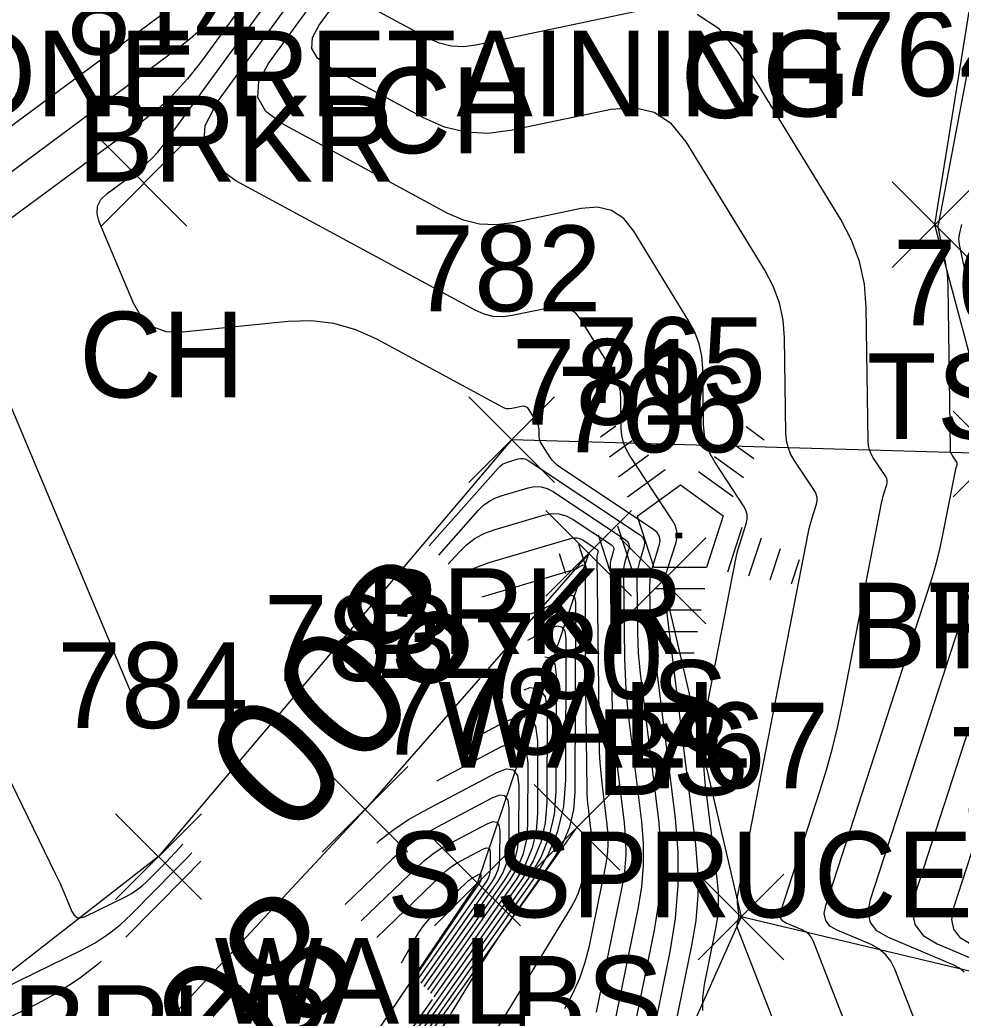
# Model space of a CAD drawing. Extents: x 1650836 to 1652450, y 332578 to 333908.
# Drawn here: x 1652049.38 to 1652071.34, y 332707.88 to 332730.94 of the extents above; entities that cross this region are included whole.
import ezdxf

# ---------------------------------------------------------------- set-up
doc = ezdxf.new("R2010")
doc.units = 0
for name, color, linetype in [('L_A', 7, 'Continuous'), ('L_C', 7, 'Continuous'), ('L_I', 7, 'Continuous'), ('L_TIC', 7, 'Continuous'), ('LAWE', 7, 'Continuous'), ('LELB', 7, 'Continuous'), ('LSOGCMA', 7, 'Continuous'), ('LSOGCMA_T', 7, 'Continuous'), ('LSOGCMI', 7, 'Continuous'), ('LTC', 7, 'Continuous'), ('LW', 7, 'Continuous')]:
    doc.layers.add(name, color=color, linetype=linetype)

msp = doc.modelspace()

# ---------------------------------------------------------------- linework, layer by layer
at = {"layer": 'L_TIC'}
for points in [[(1652051.274, 332726.131), (1652053.274, 332728.131)], [(1652053.274, 332726.131), (1652051.274, 332728.131)], [(1652069.729, 332725.162), (1652071.729, 332727.162)], [(1652071.729, 332725.162), (1652069.729, 332727.162)], [(1652059.852, 332720.144), (1652061.852, 332722.144)], [(1652061.852, 332720.144), (1652059.852, 332722.144)], [(1652071.158, 332719.813), (1652073.158, 332721.813)], [(1652073.158, 332719.813), (1652071.158, 332721.813)], [(1652071.158, 332719.813), (1652073.158, 332721.813)], [(1652073.158, 332719.813), (1652071.158, 332721.813)], [(1652061.652, 332717.494), (1652063.652, 332719.494)], [(1652063.652, 332717.494), (1652061.652, 332719.494)], [(1652063.381, 332716.853), (1652065.381, 332718.853)], [(1652065.381, 332716.853), (1652063.381, 332718.853)], [(1652056.435, 332711.519), (1652058.435, 332713.519)], [(1652058.435, 332711.519), (1652056.435, 332713.519)], [(1652061.38, 332711.103), (1652063.38, 332713.103)], [(1652063.38, 332711.103), (1652061.38, 332713.103)], [(1652051.615, 332710.419), (1652053.615, 332712.419)], [(1652053.615, 332710.419), (1652051.615, 332712.419)], [(1652059.057, 332709.801), (1652061.057, 332711.801)], [(1652061.057, 332709.801), (1652059.057, 332711.801)], [(1652065.208, 332709.013), (1652067.208, 332711.013)], [(1652067.208, 332709.013), (1652065.208, 332711.013)], [(1652065.208, 332709.013), (1652067.208, 332711.013)], [(1652067.208, 332709.013), (1652065.208, 332711.013)]]:
    msp.add_lwpolyline(points, dxfattribs=at)
at = {"layer": 'LAWE'}
msp.add_lwpolyline([(1652113.729, 332729.971), (1652105.001, 332721.607), (1652097.708, 332720.127), (1652089.433, 332715.148), (1652085.656, 332707.437), (1652080.101, 332708.542), (1652073.451, 332709.446), (1652072.158, 332720.813), (1652060.852, 332721.144), (1652052.615, 332711.419), (1652043.802, 332704.554), (1652032.724, 332702.068), (1652025.188, 332702.458), (1652014.024, 332714.079), (1651995.915, 332712.612)], dxfattribs=at)
at = {"layer": 'LELB'}
for points in [[(1652072.158, 332720.813), (1652070.729, 332726.162), (1652073.187, 332741.436)], [(1652064.381, 332717.853), (1652066.208, 332710.013), (1652062.736, 332702.235), (1652040.399, 332672.943)], [(1652040.117, 332681.915), (1652050.149, 332694.94), (1652062.38, 332712.103)]]:
    msp.add_lwpolyline(points, dxfattribs=at)
at = {"layer": 'LSOGCMA'}
for points in [[(1652054.097, 332732.112), (1652041.239, 332722.59)], [(1652059.376, 332718.24), (1652059.619, 332718.515), (1652059.802, 332718.695), (1652060.004, 332718.845), (1652060.226, 332718.965), (1652060.467, 332719.054), (1652061.599, 332719.389), (1652061.781, 332719.424), (1652061.958, 332719.418), (1652062.128, 332719.371), (1652062.292, 332719.284), (1652063.184, 332718.69), (1652063.214, 332718.664), (1652063.232, 332718.633), (1652063.238, 332718.598), (1652063.231, 332718.558), (1652063.18, 332718.391), (1652063.168, 332718.35), (1652063.161, 332718.307), (1652063.156, 332718.264), (1652063.155, 332718.221), (1652063.193, 332715.225), (1652063.203, 332714.846), (1652063.223, 332714.467), (1652063.254, 332714.089), (1652063.296, 332713.712), (1652063.483, 332712.204), (1652063.514, 332711.828), (1652063.515, 332711.453), (1652063.485, 332711.079), (1652063.424, 332710.706), (1652062.829, 332707.787)], [(1652072.286, 332716.76), (1652070.262, 332710.53), (1652070.196, 332710.153), (1652070.261, 332709.836), (1652070.457, 332709.58), (1652070.785, 332709.383), (1652073.122, 332708.394)], [(1652058.811, 332708.39), (1652060.536, 332710.848), (1652060.649, 332711.036), (1652060.729, 332711.233), (1652060.777, 332711.441), (1652060.794, 332711.659), (1652060.797, 332712.551), (1652060.773, 332712.734), (1652060.699, 332712.834), (1652060.576, 332712.853), (1652060.404, 332712.789), (1652059.097, 332712.1), (1652058.82, 332711.942), (1652058.556, 332711.765), (1652058.306, 332711.57), (1652058.068, 332711.357), (1652056.971, 332710.3)], [(1652048.634, 332708.171), (1652050.822, 332709.238), (1652051.14, 332709.41), (1652051.439, 332709.607), (1652051.721, 332709.828), (1652051.986, 332710.074), (1652053.007, 332711.108), (1652053.26, 332711.368), (1652053.392, 332711.508)]]:
    msp.add_lwpolyline(points, dxfattribs=at)
at = {"layer": 'LSOGCMI'}
for points in [[(1652070.398, 332707.235), (1652069.793, 332708.795), (1652069.7, 332708.981), (1652069.577, 332709.138), (1652069.424, 332709.266), (1652069.24, 332709.365), (1652068.446, 332709.701), (1652068.281, 332709.8), (1652068.181, 332709.93), (1652068.149, 332710.089), (1652068.182, 332710.279), (1652070.643, 332717.856), (1652070.721, 332718.11), (1652070.792, 332718.366), (1652070.854, 332718.625), (1652070.909, 332718.885), (1652071.207, 332720.418), (1652071.211, 332720.436), (1652071.215, 332720.454), (1652071.22, 332720.471), (1652071.225, 332720.489), (1652071.248, 332720.559), (1652071.251, 332720.576), (1652071.251, 332720.593), (1652071.247, 332720.609), (1652071.239, 332720.625), (1652071.135, 332720.782), (1652071.117, 332720.814), (1652071.104, 332720.847), (1652071.096, 332720.882), (1652071.093, 332720.919), (1652071.04, 332724.732), (1652071.034, 332724.872), (1652071.022, 332725.012), (1652071.003, 332725.151), (1652070.977, 332725.29), (1652070.804, 332726.102), (1652070.803, 332726.109), (1652070.803, 332726.117), (1652070.803, 332726.125), (1652070.805, 332726.132), (1652070.813, 332726.171), (1652070.816, 332726.186), (1652070.818, 332726.194), (1652073.605, 332740.882)], [(1652067.555, 332706.068), (1652066.133, 332709.735), (1652066.123, 332709.765), (1652066.119, 332709.795), (1652066.118, 332709.825), (1652066.122, 332709.855), (1652066.148, 332709.978), (1652066.153, 332710.009), (1652066.155, 332710.04), (1652066.155, 332710.071), (1652066.152, 332710.102), (1652066.124, 332710.327), (1652066.12, 332710.375), (1652066.12, 332710.423), (1652066.124, 332710.47), (1652066.131, 332710.518), (1652067.78, 332718.993), (1652067.797, 332719.076), (1652067.817, 332719.158), (1652067.839, 332719.239), (1652067.863, 332719.32), (1652067.966, 332719.642), (1652067.982, 332719.722), (1652067.981, 332719.798), (1652067.961, 332719.873), (1652067.924, 332719.944), (1652067.446, 332720.668), (1652067.362, 332720.816), (1652067.302, 332720.971), (1652067.265, 332721.133), (1652067.251, 332721.302), (1652067.22, 332723.519), (1652067.187, 332723.938), (1652067.1, 332724.342), (1652066.958, 332724.729), (1652066.762, 332725.101), (1652064.925, 332728.094), (1652064.587, 332728.513), (1652064.183, 332728.779), (1652063.713, 332728.89), (1652063.176, 332728.848), (1652060.826, 332728.357), (1652060.299, 332728.291), (1652059.785, 332728.319), (1652059.285, 332728.439), (1652058.799, 332728.652), (1652056.583, 332729.85), (1652056.321, 332730.046), (1652056.196, 332730.272), (1652056.211, 332730.53), (1652056.364, 332730.82), (1652057.317, 332732.13)], [(1652054.969, 332731.837), (1652053.596, 332729.95), (1652053.294, 332729.566), (1652052.966, 332729.209), (1652052.611, 332728.877), (1652052.23, 332728.572), (1652049.075, 332726.235), (1652048.539, 332725.715), (1652048.247, 332725.128), (1652048.199, 332724.474), (1652048.394, 332723.754), (1652052.211, 332714.673)], [(1652063.518, 332704.125), (1652064.552, 332709.197), (1652064.678, 332709.972), (1652064.741, 332710.75), (1652064.739, 332711.53), (1652064.674, 332712.313), (1652064.12, 332716.782), (1652064.107, 332716.899), (1652064.097, 332717.017), (1652064.091, 332717.136), (1652064.087, 332717.254), (1652064.081, 332717.728), (1652064.084, 332717.846), (1652064.097, 332717.963), (1652064.118, 332718.078), (1652064.148, 332718.192), (1652064.298, 332718.677), (1652064.317, 332718.789), (1652064.301, 332718.889), (1652064.25, 332718.977), (1652064.164, 332719.052), (1652061.982, 332720.505), (1652061.919, 332720.552), (1652061.861, 332720.604), (1652061.809, 332720.662), (1652061.762, 332720.726), (1652061.547, 332721.053), (1652061.526, 332721.09), (1652061.511, 332721.128), (1652061.501, 332721.169), (1652061.498, 332721.211), (1652061.495, 332721.384), (1652061.492, 332721.426), (1652061.483, 332721.467), (1652061.469, 332721.506), (1652061.449, 332721.543), (1652061.264, 332721.846), (1652061.229, 332721.888), (1652061.189, 332721.915), (1652061.141, 332721.926), (1652061.087, 332721.922), (1652060.857, 332721.874), (1652060.8, 332721.867), (1652060.745, 332721.87), (1652060.691, 332721.883), (1652060.638, 332721.906), (1652057.709, 332723.49), (1652057.216, 332723.713), (1652056.707, 332723.856), (1652056.182, 332723.919), (1652055.642, 332723.903), (1652053.177, 332723.653), (1652052.795, 332723.665), (1652052.477, 332723.782), (1652052.222, 332724.005), (1652052.029, 332724.335), (1652051.234, 332726.226), (1652051.182, 332726.419), (1652051.195, 332726.594), (1652051.273, 332726.752), (1652051.417, 332726.891), (1652052.121, 332727.413), (1652052.291, 332727.549), (1652052.45, 332727.697), (1652052.596, 332727.857), (1652052.731, 332728.028), (1652055.384, 332731.674)], [(1652065.316, 332707.826), (1652065.313, 332708.127), (1652065.354, 332708.433), (1652065.604, 332709.661), (1652065.654, 332709.968), (1652065.679, 332710.277), (1652065.678, 332710.586), (1652065.652, 332710.897), (1652065.373, 332713.149), (1652065.333, 332713.627), (1652065.33, 332714.104), (1652065.365, 332714.58), (1652065.439, 332715.054), (1652066.066, 332718.281), (1652066.09, 332718.396), (1652066.118, 332718.51), (1652066.148, 332718.623), (1652066.182, 332718.736), (1652066.325, 332719.184), (1652066.348, 332719.294), (1652066.346, 332719.401), (1652066.318, 332719.504), (1652066.266, 332719.604), (1652065.602, 332720.611), (1652065.485, 332720.817), (1652065.401, 332721.032), (1652065.35, 332721.258), (1652065.33, 332721.493), (1652065.312, 332722.807), (1652065.289, 332723.101), (1652065.228, 332723.383), (1652065.128, 332723.655), (1652064.991, 332723.915), (1652063.704, 332726.011), (1652063.468, 332726.305), (1652063.185, 332726.491), (1652062.856, 332726.569), (1652062.48, 332726.539), (1652060.884, 332726.206), (1652060.49, 332726.157), (1652060.106, 332726.177), (1652059.733, 332726.267), (1652059.369, 332726.427), (1652055.495, 332728.522), (1652055.116, 332728.804), (1652054.936, 332729.132), (1652054.957, 332729.505), (1652055.178, 332729.923), (1652056.556, 332731.817)], [(1652064.463, 332706.412), (1652065.061, 332709.343), (1652065.156, 332709.927), (1652065.203, 332710.514), (1652065.202, 332711.102), (1652065.152, 332711.691), (1652064.398, 332717.772), (1652064.397, 332717.781), (1652064.397, 332717.79), (1652064.398, 332717.8), (1652064.4, 332717.809), (1652064.407, 332717.846), (1652064.409, 332717.855), (1652064.411, 332717.864), (1652064.413, 332717.873), (1652064.416, 332717.882), (1652064.684, 332718.726), (1652064.713, 332718.867), (1652064.71, 332719.004), (1652064.676, 332719.136), (1652064.609, 332719.264), (1652063.607, 332720.783), (1652063.524, 332720.929), (1652063.464, 332721.083), (1652063.427, 332721.243), (1652063.413, 332721.411), (1652063.404, 332722.095), (1652063.39, 332722.263), (1652063.355, 332722.425), (1652063.299, 332722.58), (1652063.22, 332722.729), (1652062.484, 332723.929), (1652062.349, 332724.096), (1652062.187, 332724.203), (1652061.998, 332724.248), (1652061.783, 332724.231), (1652060.87, 332724.04), (1652060.645, 332724.012), (1652060.425, 332724.024), (1652060.212, 332724.075), (1652060.004, 332724.166), (1652054.407, 332727.193), (1652053.91, 332727.562), (1652053.675, 332727.991), (1652053.702, 332728.479), (1652053.992, 332729.027), (1652055.799, 332731.511)], [(1652063.873, 332731.157), (1652060.022, 332730.351), (1652059.73, 332730.315), (1652059.445, 332730.331), (1652059.168, 332730.397), (1652058.899, 332730.515), (1652057.671, 332731.179)], [(1652053.857, 332731.042), (1652053.704, 332730.847), (1652053.537, 332730.665), (1652053.357, 332730.497), (1652053.163, 332730.342), (1652046.173, 332725.165)], [(1652068.977, 332706.652), (1652067.895, 332709.44), (1652067.851, 332709.528), (1652067.793, 332709.602), (1652067.721, 332709.662), (1652067.635, 332709.708), (1652067.261, 332709.866), (1652067.183, 332709.913), (1652067.137, 332709.974), (1652067.121, 332710.049), (1652067.137, 332710.139), (1652068.048, 332712.943), (1652068.202, 332713.444), (1652068.341, 332713.95), (1652068.465, 332714.46), (1652068.573, 332714.973), (1652069.494, 332719.706), (1652069.504, 332719.756), (1652069.516, 332719.806), (1652069.53, 332719.855), (1652069.544, 332719.905), (1652069.607, 332720.101), (1652069.617, 332720.149), (1652069.616, 332720.196), (1652069.604, 332720.241), (1652069.581, 332720.284), (1652069.29, 332720.725), (1652069.24, 332720.815), (1652069.203, 332720.909), (1652069.18, 332721.008), (1652069.172, 332721.11), (1652069.129, 332724.231), (1652069.086, 332724.776), (1652068.972, 332725.3), (1652068.787, 332725.804), (1652068.532, 332726.287), (1652066.145, 332730.177), (1652065.706, 332730.722), (1652065.181, 332731.066)], [(1652072.297, 332721.02), (1652071.301, 332725.701), (1652071.292, 332725.76), (1652071.289, 332725.818), (1652071.292, 332725.877), (1652071.302, 332725.935), (1652071.354, 332726.168)], [(1652058.932, 332718.667), (1652060.545, 332720.489), (1652060.591, 332720.534), (1652060.641, 332720.572), (1652060.696, 332720.601), (1652060.756, 332720.624), (1652061.006, 332720.697), (1652061.067, 332720.709), (1652061.126, 332720.707), (1652061.184, 332720.691), (1652061.239, 332720.662), (1652063.838, 332718.931), (1652063.905, 332718.872), (1652063.945, 332718.804), (1652063.957, 332718.725), (1652063.942, 332718.637), (1652063.828, 332718.265), (1652063.803, 332718.172), (1652063.785, 332718.077), (1652063.775, 332717.982), (1652063.773, 332717.885), (1652063.788, 332716.645), (1652063.795, 332716.406), (1652063.808, 332716.167), (1652063.827, 332715.929), (1652063.853, 332715.692), (1652064.277, 332712.277), (1652064.331, 332711.629), (1652064.332, 332710.984), (1652064.281, 332710.341), (1652064.176, 332709.7), (1652062.756, 332702.736)], [(1652059.154, 332718.454), (1652060.082, 332719.502), (1652060.197, 332719.615), (1652060.323, 332719.708), (1652060.461, 332719.783), (1652060.612, 332719.839), (1652061.237, 332720.024), (1652061.391, 332720.053), (1652061.54, 332720.048), (1652061.683, 332720.009), (1652061.822, 332719.936), (1652063.511, 332718.811), (1652063.559, 332718.768), (1652063.588, 332718.718), (1652063.597, 332718.662), (1652063.587, 332718.598), (1652063.504, 332718.328), (1652063.485, 332718.261), (1652063.473, 332718.192), (1652063.466, 332718.123), (1652063.464, 332718.053), (1652063.489, 332716.036), (1652063.499, 332715.676), (1652063.518, 332715.317), (1652063.548, 332714.959), (1652063.587, 332714.602), (1652063.88, 332712.24), (1652063.923, 332711.729), (1652063.924, 332711.218), (1652063.883, 332710.71), (1652063.8, 332710.203), (1652062.868, 332705.633)], [(1652071.41, 332708.723), (1652071.302, 332708.813), (1652071.172, 332708.883), (1652069.631, 332709.536), (1652069.378, 332709.687), (1652069.226, 332709.885), (1652069.176, 332710.13), (1652069.227, 332710.42), (1652072.197, 332719.564)], [(1652062.093, 332707.879), (1652062.284, 332708.226), (1652062.444, 332708.585), (1652062.572, 332708.957), (1652062.667, 332709.341), (1652063.049, 332711.209), (1652063.087, 332711.448), (1652063.106, 332711.687), (1652063.106, 332711.927), (1652063.086, 332712.168), (1652062.966, 332713.133), (1652062.94, 332713.374), (1652062.92, 332713.616), (1652062.907, 332713.859), (1652062.9, 332714.101), (1652062.846, 332718.389), (1652062.846, 332718.405), (1652062.848, 332718.422), (1652062.851, 332718.438), (1652062.856, 332718.455), (1652062.875, 332718.519), (1652062.878, 332718.534), (1652062.876, 332718.548), (1652062.869, 332718.559), (1652062.857, 332718.57), (1652062.513, 332718.799), (1652062.45, 332718.832), (1652062.385, 332718.85), (1652062.317, 332718.852), (1652062.247, 332718.839), (1652060.322, 332718.27), (1652059.991, 332718.147), (1652059.686, 332717.982), (1652059.662, 332717.965)], [(1652060.165, 332717.481), (1652062.261, 332718.101), (1652062.293, 332718.112), (1652062.325, 332718.124), (1652062.357, 332718.137), (1652062.387, 332718.153), (1652062.509, 332718.217), (1652062.536, 332718.227), (1652062.555, 332718.224), (1652062.566, 332718.208), (1652062.57, 332718.18), (1652062.566, 332716.878), (1652062.565, 332716.65), (1652062.566, 332716.421), (1652062.567, 332716.193), (1652062.57, 332715.964), (1652062.608, 332712.978), (1652062.61, 332712.871), (1652062.616, 332712.765), (1652062.625, 332712.659), (1652062.637, 332712.554), (1652062.689, 332712.132), (1652062.698, 332712.026), (1652062.698, 332711.921), (1652062.69, 332711.816), (1652062.673, 332711.712), (1652062.506, 332710.895), (1652062.464, 332710.727), (1652062.408, 332710.564), (1652062.338, 332710.407), (1652062.254, 332710.255), (1652055.206, 332698.71)], [(1652053.402, 332697.865), (1652059.941, 332708.577), (1652060.165, 332708.937), (1652060.394, 332709.293), (1652060.629, 332709.646), (1652060.87, 332709.994), (1652061.844, 332711.382), (1652062.057, 332711.739), (1652062.21, 332712.114), (1652062.302, 332712.51), (1652062.334, 332712.924), (1652062.348, 332717.34), (1652062.334, 332717.443), (1652062.292, 332717.5), (1652062.222, 332717.51), (1652062.125, 332717.474), (1652061.677, 332717.239), (1652061.564, 332717.182), (1652061.449, 332717.132), (1652061.331, 332717.088), (1652061.211, 332717.049), (1652060.755, 332716.914)], [(1652050.432, 332686.428), (1652050.426, 332694.636), (1652050.441, 332694.864), (1652050.486, 332695.083), (1652050.561, 332695.294), (1652050.667, 332695.497), (1652051.151, 332696.289), (1652051.274, 332696.486), (1652051.399, 332696.681), (1652051.528, 332696.875), (1652051.66, 332697.066), (1652061.396, 332710.933), (1652061.709, 332711.457), (1652061.933, 332712.009), (1652062.069, 332712.59), (1652062.115, 332713.199), (1652062.126, 332716.499), (1652062.102, 332716.677), (1652062.03, 332716.776), (1652061.909, 332716.794), (1652061.74, 332716.732), (1652061.226, 332716.461)], [(1652051.332, 332696.788), (1652061.252, 332710.919), (1652061.532, 332711.387), (1652061.733, 332711.88), (1652061.854, 332712.398), (1652061.895, 332712.942), (1652061.904, 332715.658), (1652061.87, 332715.912), (1652061.768, 332716.052), (1652061.629, 332716.073)], [(1652061.15, 332715.313), (1652061.283, 332715.362), (1652061.505, 332715.328), (1652061.638, 332715.147), (1652061.682, 332714.818), (1652061.675, 332712.685), (1652061.638, 332712.207), (1652061.532, 332711.751), (1652061.356, 332711.317), (1652061.109, 332710.905), (1652052.704, 332698.932)], [(1652048.404, 332714.711), (1652050.206, 332711.026), (1652050.258, 332710.917), (1652050.309, 332710.808), (1652050.358, 332710.698), (1652050.406, 332710.587), (1652050.595, 332710.142), (1652050.65, 332710.051), (1652050.72, 332710.001), (1652050.806, 332709.993), (1652050.907, 332710.025), (1652051.845, 332710.483), (1652051.982, 332710.557), (1652052.11, 332710.641), (1652052.231, 332710.736), (1652052.345, 332710.842), (1652052.783, 332711.285), (1652052.892, 332711.397), (1652052.999, 332711.51), (1652053.105, 332711.625), (1652053.181, 332711.71)], [(1652060.154, 332714.277), (1652060.714, 332714.572), (1652061.041, 332714.692), (1652061.275, 332714.657), (1652061.414, 332714.466), (1652061.46, 332714.121), (1652061.455, 332712.429), (1652061.423, 332712.016), (1652061.331, 332711.621), (1652061.179, 332711.246), (1652060.966, 332710.891), (1652059.042, 332708.15)], [(1652058.965, 332708.23), (1652060.823, 332710.876), (1652061.002, 332711.176), (1652061.13, 332711.492), (1652061.208, 332711.824), (1652061.234, 332712.172), (1652061.239, 332713.598), (1652061.2, 332713.889), (1652061.083, 332714.049), (1652060.886, 332714.079), (1652060.611, 332713.978), (1652059.101, 332713.182)], [(1652072.374, 332713.955), (1652071.162, 332710.224), (1652071.115, 332709.953), (1652071.161, 332709.726), (1652071.302, 332709.542), (1652071.538, 332709.401)], [(1652057.706, 332711.731), (1652057.782, 332711.8), (1652058.108, 332712.053), (1652058.45, 332712.283), (1652058.81, 332712.489), (1652060.507, 332713.384), (1652060.731, 332713.466), (1652060.891, 332713.441), (1652060.987, 332713.311), (1652061.018, 332713.075), (1652061.014, 332711.916), (1652060.993, 332711.633), (1652060.93, 332711.363), (1652060.825, 332711.106), (1652060.68, 332710.862), (1652058.888, 332708.31)], [(1652057.34, 332709.917), (1652058.662, 332711.191), (1652058.829, 332711.34), (1652059.005, 332711.477), (1652059.19, 332711.601), (1652059.384, 332711.712), (1652060.3, 332712.195), (1652060.421, 332712.239), (1652060.507, 332712.226), (1652060.559, 332712.156), (1652060.576, 332712.028), (1652060.574, 332711.403), (1652060.562, 332711.25), (1652060.528, 332711.104), (1652060.472, 332710.965), (1652060.393, 332710.834), (1652058.734, 332708.47)], [(1652057.709, 332709.534), (1652059.257, 332711.024), (1652059.352, 332711.11), (1652059.453, 332711.189), (1652059.559, 332711.26), (1652059.671, 332711.324), (1652060.197, 332711.601), (1652060.266, 332711.626), (1652060.315, 332711.619), (1652060.345, 332711.578), (1652060.355, 332711.505), (1652060.354, 332711.146), (1652060.347, 332711.058), (1652060.327, 332710.975), (1652060.295, 332710.895), (1652060.25, 332710.82), (1652059.044, 332709.103), (1652058.827, 332708.792), (1652058.658, 332708.549)], [(1652053.599, 332711.309), (1652053.231, 332710.93), (1652051.854, 332709.536)], [(1652058.283, 332708.938), (1652058.584, 332709.479), (1652058.685, 332709.646), (1652058.797, 332709.803), (1652058.92, 332709.952), (1652059.055, 332710.092), (1652059.851, 332710.858), (1652059.876, 332710.88), (1652059.902, 332710.901), (1652059.929, 332710.919), (1652059.958, 332710.935), (1652060.093, 332711.007), (1652060.111, 332711.013), (1652060.124, 332711.011), (1652060.131, 332711.001), (1652060.134, 332710.982), (1652060.133, 332710.89), (1652060.132, 332710.867), (1652060.127, 332710.845), (1652060.118, 332710.825), (1652060.107, 332710.806), (1652059.796, 332710.364), (1652059.74, 332710.284), (1652059.685, 332710.203), (1652059.629, 332710.123), (1652059.574, 332710.042), (1652058.599, 332708.61)], [(1652051.274, 332708.977), (1652051.212, 332708.919), (1652050.769, 332708.572), (1652050.298, 332708.263), (1652049.799, 332707.993), (1652046.362, 332706.317)], [(1652058.997, 332708.086), (1652054.076, 332701.077), (1652053.653, 332700.472), (1652053.233, 332699.866), (1652052.814, 332699.259), (1652052.398, 332698.65), (1652050.738, 332696.211), (1652050.32, 332695.603), (1652049.897, 332694.999), (1652049.469, 332694.399), (1652049.035, 332693.803), (1652044.576, 332687.729)]]:
    msp.add_lwpolyline(points, dxfattribs=at)
at = {"layer": 'LTC'}
for p, q in [((1652062.928, 332721.211), (1652063.282, 332721.468)), ((1652066.326, 332721.451), (1652066.745, 332721.146)), ((1652063.137, 332720.745), (1652063.667, 332721.129)), ((1652065.955, 332721.103), (1652066.504, 332720.704)), ((1652063.347, 332720.279), (1652064.051, 332720.791)), ((1652065.584, 332720.754), (1652066.263, 332720.261)), ((1652063.557, 332719.814), (1652064.435, 332720.451)), ((1652065.213, 332720.406), (1652066.022, 332719.817)), ((1652063.781, 332719.359), (1652064.793, 332720.093)), ((1652064.793, 332720.093), (1652065.79, 332719.368)), ((1652063.781, 332719.359), (1652064.168, 332718.165)), ((1652065.79, 332719.368), (1652065.399, 332718.165)), ((1652063.327, 332719.139), (1652063.657, 332718.12)), ((1652066.227, 332719.097), (1652065.889, 332718.058)), ((1652062.871, 332718.923), (1652063.142, 332718.088)), ((1652066.672, 332718.847), (1652066.384, 332717.962)), ((1652061.96, 332718.49), (1652062.112, 332718.022)), ((1652062.416, 332718.706), (1652062.627, 332718.055)), ((1652067.117, 332718.597), (1652066.879, 332717.867)), ((1652067.561, 332718.346), (1652067.374, 332717.772)), ((1652065.399, 332718.165), (1652064.168, 332718.165)), ((1652065.36, 332717.665), (1652064.216, 332717.665)), ((1652065.277, 332717.165), (1652064.288, 332717.165)), ((1652065.193, 332716.665), (1652064.361, 332716.665)), ((1652065.109, 332716.165), (1652064.434, 332716.165))]:
    msp.add_line(p, q, dxfattribs=at)
at = {"layer": 'LW'}
for points in [[(1652113.729, 332729.971), (1652107.656, 332717.052), (1652097.986, 332712.237), (1652094.942, 332714.723), (1652087.881, 332709.509), (1652086.261, 332705.252), (1652079.661, 332707.671), (1652073.141, 332708.362), (1652066.208, 332710.013)], [(1652039.797, 332682.479), (1652049.446, 332695.09), (1652060.057, 332710.801), (1652062.652, 332718.494), (1652057.435, 332712.519), (1652045.373, 332699.585), (1652034.38, 332697.584), (1652022.272, 332696.192), (1652013.872, 332713.448), (1651995.92, 332711.781)]]:
    msp.add_lwpolyline(points, dxfattribs=at)

# ---------------------------------------------------------------- texts
at = {"layer": 'L_A'}
for s, p in [('CH', (1652064.795, 332728.652)), ('CH', (1652057.511, 332727.83)), ('BRKR', (1652050.717, 332727.169)), ('CH', (1652050.762, 332722.131)), ('TS', (1652069.139, 332721.162)), ('BRKR', (1652057.443, 332716.144)), ('BRKR', (1652068.748, 332715.813)), ('TS', (1652070.567, 332715.813)), ('S', (1652064.118, 332714.002)), ('WALL', (1652059.141, 332713.494)), ('BS', (1652062.822, 332712.853)), ('WALL', (1652053.924, 332707.519)), ('BS', (1652060.821, 332707.103)), ('BRKR', (1652049.205, 332706.419))]:
    msp.add_text(s, height=2, dxfattribs=at).set_placement(p)
at = {"layer": 'L_C'}
for s, p in [('STONE RETAINING', (1652044.261, 332728.688)), ('S.SPRUCE', (1652057.945, 332710.002))]:
    msp.add_text(s, height=2, dxfattribs=at).set_placement(p)
at = {"layer": 'L_I'}
for s, p in [('814', (1652050.479, 332730.131)), ('764', (1652068.32, 332729.162)), ('782', (1652058.49, 332724.144)), ('763', (1652069.748, 332723.813)), ('763', (1652069.748, 332723.813)), ('765', (1652062.323, 332722.002)), ('781', (1652060.857, 332721.494)), ('766', (1652061.917, 332720.853)), ('783', (1652055.073, 332715.519)), ('780', (1652059.931, 332715.103)), ('784', (1652050.252, 332714.419)), ('778', (1652057.695, 332713.801)), ('767', (1652063.799, 332713.013)), ('767', (1652063.799, 332713.013)), ('762', (1652071.041, 332712.446))]:
    msp.add_text(s, height=2, dxfattribs=at).set_placement(p)
at = {"layer": 'LSOGCMA_T'}
for s, rotation, p in [('800', 226.1184, (1652058.14, 332718.675)), ('805', 223.928, (1652055.446, 332710.913))]:
    msp.add_text(s, height=3, rotation=rotation, dxfattribs=at).set_placement(p)
at = {"layer": 'LTC'}
msp.add_text('.', height=1.037, rotation=270, dxfattribs=at).set_placement((1652064.675, 332719.106))

doc.saveas('drawing.dxf')
